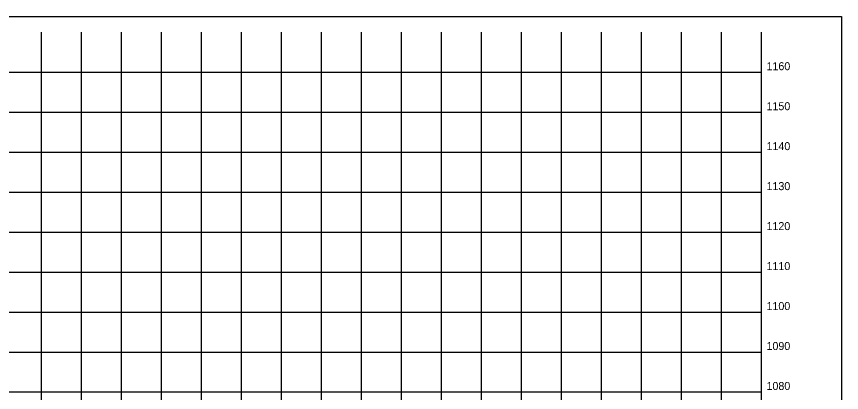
# Model space of a CAD drawing. Extents: x 5868 to 6683, y 2883 to 19120.
# Drawn here: x 6157.6 to 6363.8, y 5511.9 to 5606 of the extents above; entities that cross this region are included whole.
import ezdxf

# ---------------------------------------------------------------- set-up
doc = ezdxf.new("R2010")
doc.units = 0
for name, color, linetype in [('DESIGN - SHEET - Corner Text', 7, 'Continuous'), ('DESIGN - SHEET - Linework', 7, 'Continuous'), ('DESIGN - SHEET - Plot Shape', 7, 'Continuous')]:
    doc.layers.add(name, color=color, linetype=linetype)

msp = doc.modelspace()

# ---------------------------------------------------------------- linework, layer by layer
at = {"layer": 'DESIGN - SHEET - Linework'}
for p, q in [((6163.78, 5392.07), (6163.78, 5602.07)), ((6173.78, 5392.07), (6173.78, 5602.07)), ((6183.78, 5392.07), (6183.78, 5602.07)), ((6193.78, 5392.07), (6193.78, 5602.07)), ((6203.78, 5392.07), (6203.78, 5602.07)), ((6213.78, 5392.07), (6213.78, 5602.07)), ((6223.78, 5392.07), (6223.78, 5602.07)), ((6233.78, 5392.07), (6233.78, 5602.07)), ((6243.78, 5392.07), (6243.78, 5602.07)), ((6253.78, 5392.07), (6253.78, 5602.07)), ((6263.78, 5392.07), (6263.78, 5602.07)), ((6273.78, 5392.07), (6273.78, 5602.07)), ((6283.78, 5392.07), (6283.78, 5602.07)), ((6293.78, 5392.07), (6293.78, 5602.07)), ((6303.78, 5392.07), (6303.78, 5602.07)), ((6313.78, 5392.07), (6313.78, 5602.07)), ((6323.78, 5392.07), (6323.78, 5602.07)), ((6333.78, 5392.07), (6333.78, 5602.07)), ((6043.78, 5592.07), (6343.78, 5592.07)), ((6043.78, 5582.07), (6343.78, 5582.07)), ((6043.78, 5572.07), (6343.78, 5572.07)), ((6043.78, 5562.07), (6343.78, 5562.07)), ((6043.78, 5552.07), (6343.78, 5552.07)), ((6043.78, 5542.07), (6343.78, 5542.07)), ((6043.78, 5532.07), (6343.78, 5532.07)), ((6043.78, 5522.07), (6343.78, 5522.07)), ((6043.78, 5512.07), (6343.78, 5512.07))]:
    msp.add_line(p, q, dxfattribs=at)
msp.add_lwpolyline([(6043.78, 5602.07), (6043.78, 5392.07), (6343.78, 5392.07), (6343.78, 5602.07)], dxfattribs=at)
at = {"layer": 'DESIGN - SHEET - Plot Shape'}
msp.add_lwpolyline([(6023.78, 5606.01), (6363.78, 5606.01), (6363.78, 5388.13), (6023.78, 5388.13)], close=True, dxfattribs=at)

# ---------------------------------------------------------------- texts
at = {"layer": 'DESIGN - SHEET - Corner Text'}
for s, p in [('1160', (6345.03, 5592.57)), ('1150', (6345.03, 5582.57)), ('1140', (6345.03, 5572.57)), ('1130', (6345.03, 5562.57)), ('1120', (6345.03, 5552.57)), ('1110', (6345.03, 5542.57)), ('1100', (6345.03, 5532.57)), ('1090', (6345.03, 5522.57)), ('1080', (6345.03, 5512.57))]:
    msp.add_text(s, height=2, dxfattribs=at).set_placement(p)

doc.saveas('drawing.dxf')
